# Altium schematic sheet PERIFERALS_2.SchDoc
size A4; PageSetup: Record=PageOptions|CenterHorizontal=True|CenterVertical=True|PrintScale=0.70|XCorrection=1.00|YCorrection=1.00|PrintKind=0|BorderSize=5000000|LeftOffset=5|BottomOffset=0|Orientation=1|PaperLength=1000|PaperWidth=1000|Scale=100|PaperSource=7|PrintQuality=-4|MediaType=1|DitherType=10|PaperKind=A4|PrintScaleMode=1
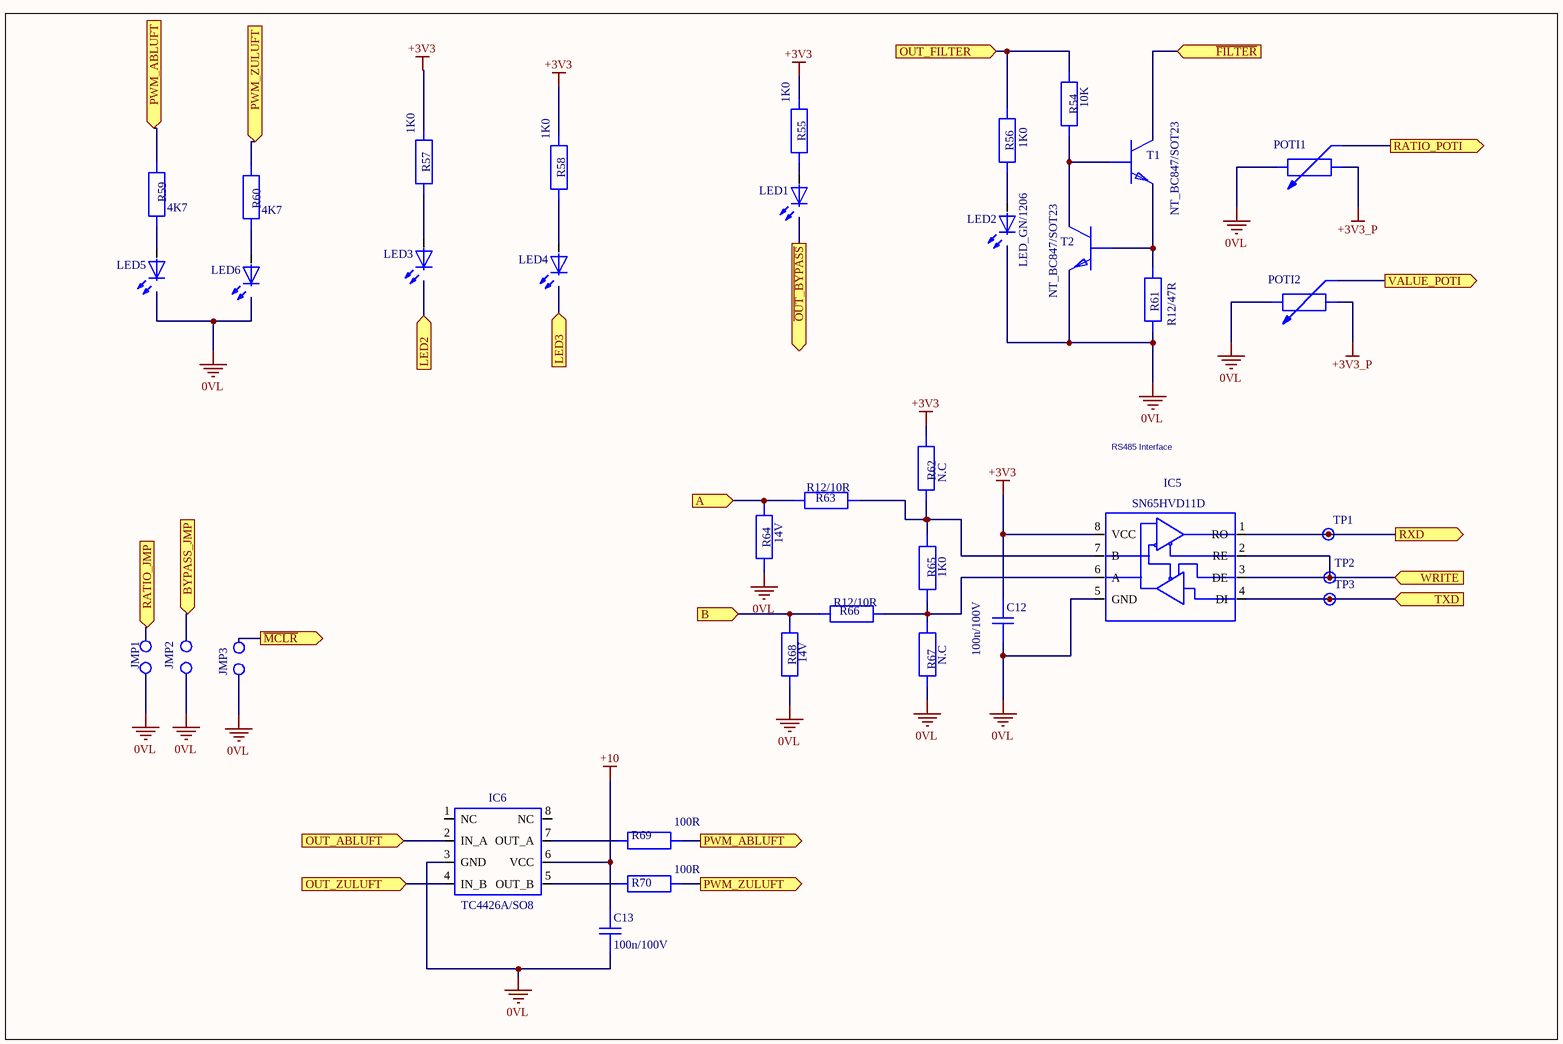
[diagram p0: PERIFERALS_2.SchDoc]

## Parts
C12  value 100n/100V  (hidden comment: C12/100N)
C13  value 100n/100V  (hidden comment: C12/100N)
IC5  SN65HVD11D
IC6  TC4426A/SO8
JMP1  JUMPER2  (value not drawn)
JMP2  JUMPER2  (value not drawn)
JMP3  JUMPER2  (value not drawn)
LED1  LED_GN/1206  (value not drawn)
LED2  LED_GN/1206
LED3  LED_GN/1206  (value not drawn)
LED4  LED_GN/1206  (value not drawn)
LED5  LED_GN/1206  (value not drawn)
LED6  LED_GN/1206  (value not drawn)
POTI1  ST_CA9V/100K  (value not drawn)
POTI2  ST_CA9V/100K  (value not drawn)
R54  value 10K  (hidden comment: R12/10K)
R55  value 1K0  (hidden comment: R12/1K0)
R56  value 1K0  (hidden comment: R12/1K0)
R57  value 1K0  (hidden comment: R12/1K0)
R58  value 1K0  (hidden comment: R12/1K0)
R59  value 4K7  (hidden comment: R12/4K7)
R60  value 4K7  (hidden comment: R12/4K7)
R61  R12/47R
R62  value N.C  (hidden comment: R12/NC)
R63  R12/10R
R64  value 14V  (hidden comment: R12/VARISTOR_14V)
R65  value 1K0  (hidden comment: R12/1K)
R66  R12/10R
R67  value N.C  (hidden comment: R12/NC)
R68  value 14V  (hidden comment: R12/VARISTOR_14V)
R69  value 100R  (hidden comment: R12/100R)
R70  value 100R  (hidden comment: R12/100R)
T1  NT_BC847/SOT23
T2  NT_BC847/SOT23
TP1  LP10  (value not drawn)  (no BOM)
TP2  LP10  (value not drawn)  (no BOM)
TP3  LP10  (value not drawn)  (no BOM)

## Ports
A, B, BYPASS_JMP, LED2, LED3, OUT_ABLUFT, OUT_FILTER, OUT_ZULUFT, PWM_ABLUFT, PWM_ZULUFT, RATIO_JMP, RATIO_POTI, RXD, TXD, VALUE_POTI, WRITE, ~{FILTER}, ~{MCLR}, ~{OUT_BYPASS}

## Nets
0VL: C12.1 C13.1 IC5.5(GND) IC6.3(GND) JMP1.1 JMP2.1 JMP3.1 LED2.K LED5.K LED6.K POTI1.1 POTI2.1 R61.1 R64.1 R67.1 R68.1 T2.E
+3V3: C12.2 IC5.8(VCC) R55.2 R57.2 R58.2 R62.2
+3V3_P: POTI1.2 POTI2.2
+10: C13.2 IC6.6(VCC)
~{FILTER}: T1.C ; port ~{FILTER}
~{MCLR}: JMP3.2 ; port ~{MCLR}
~{OUT_BYPASS}: LED1.K ; port ~{OUT_BYPASS}
A: R63.1 R64.2 ; port A
B: R66.1 R68.2 ; port B
BYPASS_JMP: JMP2.2 ; port BYPASS_JMP
LED2: LED3.K ; port LED2
LED3: LED4.K ; port LED3
OUT_ABLUFT: IC6.2(IN_A) ; port OUT_ABLUFT
OUT_FILTER: R54.2 R56.2 ; port OUT_FILTER
OUT_ZULUFT: IC6.4(IN_B) ; port OUT_ZULUFT
PWM_ABLUFT: R59.2 R69.1 ; port PWM_ABLUFT
PWM_ZULUFT: R60.2 R70.1 ; port PWM_ZULUFT
RATIO_JMP: JMP1.2 ; port RATIO_JMP
RATIO_POTI: POTI1.3 ; port RATIO_POTI
RXD: IC5.1(RO) TP1.1 ; port RXD
TXD: IC5.4(DI) TP3.1 ; port TXD
VALUE_POTI: POTI2.3 ; port VALUE_POTI
WRITE: IC5.2(RE) IC5.3(DE) TP2.1 ; port WRITE
NetIC5_6: IC5.6(A) R65.1 R66.2 R67.2
NetIC5_7: IC5.7(B) R62.1 R63.2 R65.2
NetIC6_5: IC6.5(OUT_B) R70.2
NetIC6_7: IC6.7(OUT_A) R69.2
NetLED1_A: LED1.A R55.1
NetLED2_A: LED2.A R56.1
NetLED3_A: LED3.A R57.1
NetLED4_A: LED4.A R58.1
NetLED5_A: LED5.A R59.1
NetLED6_A: LED6.A R60.1
NetR54_1: R54.1 T1.B T2.C
NetR61_2: R61.2 T1.E T2.B

Not connected (* = marked no-connect by the designer): IC6 1(NC) 8(NC)

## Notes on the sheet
- RS485 Interface

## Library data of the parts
C12 C13 = C12/100N: PART DESCE: CHIP-CAP. CERAMIC 0.10UF 100V X7R 10% 1206; Geometry.Height: 0.99mm; TYPE: B37872K1104K062; MFG.#1: EPCOS; GR: C; SUPP.#1: BUERKLIN; SUPP.ART.#1: 52 D 975; PCB DECAL: R02X125Y0A0; SUPP.ART.#2: 399-1805-1-ND; SUPP.#2: DIGIKEY; TYPE.#2: C1206C104K1RACTU
IC5 = SN65HVD11D: PART DESCE: RS485 INTERFACE TRANSCEIVER 3V3; MFG.#1: TEXAS INSTRUMENTS; GR: U8; SUPP.#1: FARNELL; SUPP.ART.#1: 1100955; Geometry.Height: 1.75mm; PCB DECAL: US08X150Y230A0
IC6 = TC4426A/SO8: PART DESCE: MOSFET DRIVER; MFG.#1: MICROCHIP; GR: U6; Geometry.Height: 1.75mm; PCB DECAL: US08X150Y230A0
JMP1-JMP3 = JUMPER2: PART DESCE: PIN HEADER 2 POL. 6,7mm; VALUE: 2/0; MFG.#1: AMP; GR: BR; SUPP.#1: BUERKLIN; SUPP.ART.#1: 59 F 2124; PCB DECAL: BR02X100Y0A35
LED1-LED6 = LED_GN/1206: PART DESCE: LED GREEN max.30mA; TYPE: QTLP650C-4; VALUE: GREEN; GR: LA; PCB DECAL: O02X150Y0A0; SUPP.ART.#1: 359-9784; SUPP.#1: FARNELL; MFG.#1: FAIRCHILD
POTI1 POTI2 = ST_CA9V/100K: PART DESCE: Potentiometer RM15mm 100K; SUPP.ART.#1: 7135/104; SUPP.#1: MIRA; GR: P; MFG.#1: ACP; VALUE: 100K /0.25W; Geometry.Height: 7.0mm; PCB DECAL: POTI_CA9V_NEU
R54 = R12/10K: PART DESCE: MINI-MELF 1% 1/4W; Geometry.Height: 3.20040mm; MFG.#1: BEYSCHLAG; GR: R; SUPP.#1: BUERKLIN; SUPP.ART.#1: 06 E 760; PCB DECAL: R02X125Y0A0
R55-R58 = R12/1K0: PART DESCE: MINI-MELF 1% 1/4W or 1206; GR: R4; PCB DECAL: R02X125Y0A0; MFG.#1: BEYSCHLAG; SUPP.#1: BUERKLIN; SUPP.ART.#1: 06 E 664; Geometry.Height: 3.20040mm
R59 R60 = R12/4K7: PART DESCE: MINI-MELF 1% 1/4W; GR: R; PCB DECAL: R02X125Y0A0; MFG.#1: BEYSCHLAG; SUPP.#1: BUERKLIN; SUPP.ART.#1: 06 E 728; Geometry.Height: 3.20040mm
R61 = R12/47R: PART DESCE: MINI-MELF 1% 1/4W; Geometry.Height: 3.20040mm; VALUE: 47R; MFG.#1: BEYSCHLAG; GR: R; SUPP.#1: BUERKLIN; SUPP.ART.#1: 06 E 536; PCB DECAL: R02X125Y0A0
R62 R67 = R12/NC: PART DESCE: MINI-MELF 1% 1/4W; Geometry.Height: 3.20040mm; MFG.#1: BEYSCHLAG; GR: R; PCB DECAL: R02X125Y0A0
R63 R66 = R12/10R: PART DESCE: MINI-MELF 1% 1/4W; Geometry.Height: 3.20040mm; VALUE: 10R; MFG.#1: VITROHM; GR: R; SUPP.#1: BUERKLIN; SUPP.ART.#1: 26 E 200; PCB DECAL: R02X125Y0A0
R64 R68 = R12/VARISTOR_14V: PART DESCE: VARISTOR SMD 1206 14V; MFG.#1: WUERTH; GR: R4; SUPP.ART.#1: 825 31 140; PCB DECAL: R02X125Y0A0
R65 = R12/1K: PART DESCE: RESISTOR SMD 1206 1% 1K0 0.125W; Geometry.Height: 0.55mm; MFG.#1: MULTICOMP; GR: R; SUPP.#1: FARNELL; SUPP.ART.#1: 9335757; PCB DECAL: R02X125Y0A0
R69 R70 = R12/100R: PART DESCE: RESISTOR SMD 1206 5%; Geometry.Height: 0.55mm; GR: R3; PCB DECAL: R02X125Y0A0
T1 T2 = NT_BC847/SOT23: PART DESCE: TRANSISTOR NPN SOT23; TYPE: BC847B; VALUE: 45V/0A1; MFG.#1: SIEMENS; GR: T1; SUPP.#1: BUERKLIN; SUPP.ART.#1: 12 S 6268; Geometry.Height: 1.09mm; PCB DECAL: TR03X80Y95A0
TP1-TP3 = LP10: PART DESCE: SOLDER PIN 0,9 mm; MFG.#1: ETTINGER; GR: TP; SUPP.#1: BUERKLIN; SUPP.ART.#1: 12 H 6158; PCB DECAL: TP01X0Y0B39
